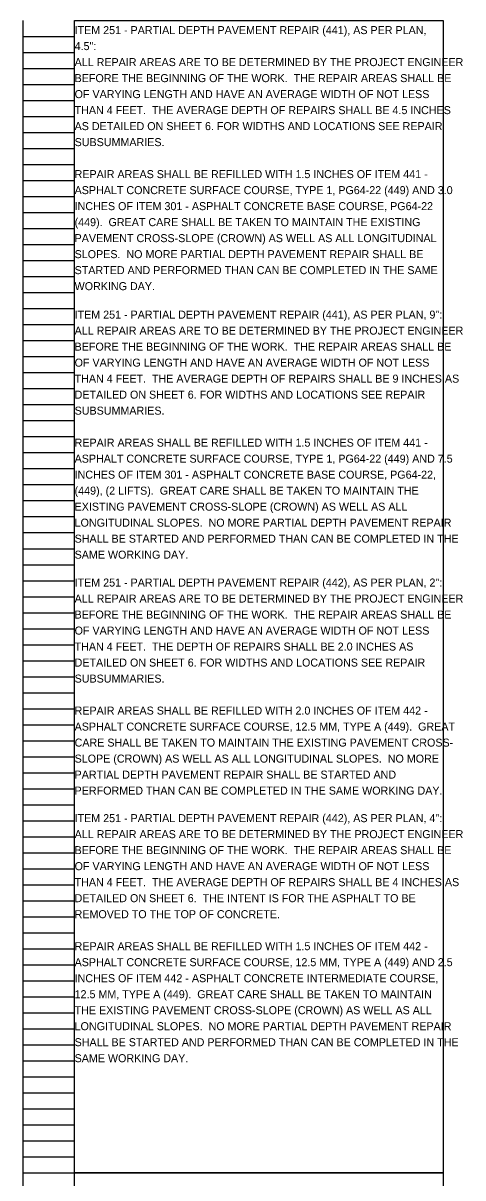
# Model space of a CAD drawing. Extents: x 16463 to 16495, y 5662 to 5823.
# Drawn here: x 16463.05 to 16470.73, y 5783.06 to 5803.27 of the extents above; entities that cross this region are included whole.
import ezdxf

# ---------------------------------------------------------------- set-up
doc = ezdxf.new("R2010")
doc.units = 0
for name, color, linetype in [('Default', 7, 'Continuous'), ('SC_Scratch1', 7, 'Continuous'), ('SH_Data', 7, 'Continuous')]:
    doc.layers.add(name, color=color, linetype=linetype)

msp = doc.modelspace()

# ---------------------------------------------------------------- linework, layer by layer
at = {"layer": 'SC_Scratch1'}
for points in [[(16463.949, 5803.312), (16470.389, 5803.312), (16470.389, 5783.152), (16463.949, 5783.152)], [(16463.949, 5783.152), (16470.389, 5783.152), (16470.389, 5762.992), (16463.949, 5762.992)]]:
    msp.add_lwpolyline(points, close=True, dxfattribs=at)
at = {"layer": 'SH_Data'}
for p, q in [((16463.049, 5783.152), (16463.049, 5803.312)), ((16463.949, 5783.152), (16463.949, 5803.312)), ((16463.049, 5803.032), (16463.949, 5803.032)), ((16463.049, 5802.752), (16463.949, 5802.752)), ((16463.049, 5802.472), (16463.949, 5802.472)), ((16463.049, 5802.192), (16463.949, 5802.192)), ((16463.049, 5801.912), (16463.949, 5801.912)), ((16463.049, 5801.632), (16463.949, 5801.632)), ((16463.049, 5801.352), (16463.949, 5801.352)), ((16463.049, 5801.072), (16463.949, 5801.072)), ((16463.049, 5800.792), (16463.949, 5800.792)), ((16463.049, 5800.512), (16463.949, 5800.512)), ((16463.049, 5800.232), (16463.949, 5800.232)), ((16463.049, 5799.952), (16463.949, 5799.952)), ((16463.049, 5799.672), (16463.949, 5799.672)), ((16463.049, 5799.392), (16463.949, 5799.392)), ((16463.049, 5799.112), (16463.949, 5799.112)), ((16463.049, 5798.832), (16463.949, 5798.832)), ((16463.049, 5798.552), (16463.949, 5798.552)), ((16463.049, 5798.272), (16463.949, 5798.272)), ((16463.049, 5797.992), (16463.949, 5797.992)), ((16463.049, 5797.712), (16463.949, 5797.712)), ((16463.049, 5797.432), (16463.949, 5797.432)), ((16463.049, 5797.152), (16463.949, 5797.152)), ((16463.049, 5796.872), (16463.949, 5796.872)), ((16463.049, 5796.592), (16463.949, 5796.592)), ((16463.049, 5796.312), (16463.949, 5796.312)), ((16463.049, 5796.032), (16463.949, 5796.032)), ((16463.049, 5795.752), (16463.949, 5795.752)), ((16463.049, 5795.472), (16463.949, 5795.472)), ((16463.049, 5795.192), (16463.949, 5795.192)), ((16463.049, 5794.912), (16463.949, 5794.912)), ((16463.049, 5794.632), (16463.949, 5794.632)), ((16463.049, 5794.352), (16463.949, 5794.352)), ((16463.049, 5794.072), (16463.949, 5794.072)), ((16463.049, 5793.792), (16463.949, 5793.792)), ((16463.049, 5793.512), (16463.949, 5793.512)), ((16463.049, 5793.232), (16463.949, 5793.232)), ((16463.049, 5792.952), (16463.949, 5792.952)), ((16463.049, 5792.672), (16463.949, 5792.672)), ((16463.049, 5792.392), (16463.949, 5792.392)), ((16463.049, 5792.112), (16463.949, 5792.112)), ((16463.049, 5791.832), (16463.949, 5791.832)), ((16463.049, 5791.552), (16463.949, 5791.552)), ((16463.049, 5791.272), (16463.949, 5791.272)), ((16463.049, 5790.992), (16463.949, 5790.992)), ((16463.049, 5790.712), (16463.949, 5790.712)), ((16463.049, 5790.432), (16463.949, 5790.432)), ((16463.049, 5790.152), (16463.949, 5790.152)), ((16463.049, 5789.872), (16463.949, 5789.872)), ((16463.049, 5789.592), (16463.949, 5789.592)), ((16463.049, 5789.312), (16463.949, 5789.312)), ((16463.049, 5789.032), (16463.949, 5789.032)), ((16463.049, 5788.752), (16463.949, 5788.752)), ((16463.049, 5788.472), (16463.949, 5788.472)), ((16463.049, 5788.192), (16463.949, 5788.192)), ((16463.049, 5787.912), (16463.949, 5787.912)), ((16463.049, 5787.632), (16463.949, 5787.632)), ((16463.049, 5787.352), (16463.949, 5787.352)), ((16463.049, 5787.072), (16463.949, 5787.072)), ((16463.049, 5786.792), (16463.949, 5786.792)), ((16463.049, 5786.512), (16463.949, 5786.512)), ((16463.049, 5786.232), (16463.949, 5786.232)), ((16463.049, 5785.952), (16463.949, 5785.952)), ((16463.049, 5785.672), (16463.949, 5785.672)), ((16463.049, 5785.392), (16463.949, 5785.392)), ((16463.049, 5785.112), (16463.949, 5785.112)), ((16463.049, 5784.832), (16463.949, 5784.832)), ((16463.049, 5784.552), (16463.949, 5784.552)), ((16463.049, 5784.272), (16463.949, 5784.272)), ((16463.049, 5783.992), (16463.949, 5783.992)), ((16463.049, 5783.712), (16463.949, 5783.712)), ((16463.049, 5783.432), (16463.949, 5783.432)), ((16463.049, 5762.992), (16463.049, 5783.152)), ((16463.049, 5783.152), (16463.949, 5783.152)), ((16463.049, 5783.152), (16463.949, 5783.152)), ((16463.949, 5762.992), (16463.949, 5783.152))]:
    msp.add_line(p, q, dxfattribs=at)

# ---------------------------------------------------------------- texts
at = {"layer": 'Default'}
for s, p in [('ITEM 251 - PARTIAL DEPTH PAVEMENT REPAIR (441), AS PER PLAN, ', (16463.949, 5803.075)), ('4.5":', (16463.949, 5802.795)), ('ALL REPAIR AREAS ARE TO BE DETERMINED BY THE PROJECT ENGINEER ', (16463.949, 5802.515)), ('BEFORE THE BEGINNING OF THE WORK.  THE REPAIR AREAS SHALL BE ', (16463.949, 5802.235)), ('OF VARYING LENGTH AND HAVE AN AVERAGE WIDTH OF NOT LESS ', (16463.949, 5801.955)), ('THAN 4 FEET.  THE AVERAGE DEPTH OF REPAIRS SHALL BE 4.5 INCHES ', (16463.949, 5801.675)), ('AS DETAILED ON SHEET 6. FOR WIDTHS AND LOCATIONS SEE REPAIR ', (16463.949, 5801.395)), ('SUBSUMMARIES.  ', (16463.949, 5801.115)), ('REPAIR AREAS SHALL BE REFILLED WITH 1.5 INCHES OF ITEM 441 - ', (16463.949, 5800.555)), ('ASPHALT CONCRETE SURFACE COURSE, TYPE 1, PG64-22 (449) AND 3.0 ', (16463.949, 5800.275)), ('INCHES OF ITEM 301 - ASPHALT CONCRETE BASE COURSE, PG64-22 ', (16463.949, 5799.995)), ('(449).  GREAT CARE SHALL BE TAKEN TO MAINTAIN THE EXISTING ', (16463.949, 5799.715)), ('PAVEMENT CROSS-SLOPE (CROWN) AS WELL AS ALL LONGITUDINAL ', (16463.949, 5799.435)), ('SLOPES.  NO MORE PARTIAL DEPTH PAVEMENT REPAIR SHALL BE ', (16463.949, 5799.155)), ('STARTED AND PERFORMED THAN CAN BE COMPLETED IN THE SAME ', (16463.949, 5798.875)), ('WORKING DAY.', (16463.949, 5798.595)), ('ITEM 251 - PARTIAL DEPTH PAVEMENT REPAIR (441), AS PER PLAN, 9":', (16463.949, 5798.097)), ('ALL REPAIR AREAS ARE TO BE DETERMINED BY THE PROJECT ENGINEER ', (16463.949, 5797.817)), ('BEFORE THE BEGINNING OF THE WORK.  THE REPAIR AREAS SHALL BE ', (16463.949, 5797.537)), ('OF VARYING LENGTH AND HAVE AN AVERAGE WIDTH OF NOT LESS ', (16463.949, 5797.257)), ('THAN 4 FEET.  THE AVERAGE DEPTH OF REPAIRS SHALL BE 9 INCHES AS ', (16463.949, 5796.977)), ('DETAILED ON SHEET 6. FOR WIDTHS AND LOCATIONS SEE REPAIR ', (16463.949, 5796.697)), ('SUBSUMMARIES.  ', (16463.949, 5796.417)), ('REPAIR AREAS SHALL BE REFILLED WITH 1.5 INCHES OF ITEM 441 - ', (16463.949, 5795.857)), ('ASPHALT CONCRETE SURFACE COURSE, TYPE 1, PG64-22 (449) AND 7.5 ', (16463.949, 5795.577)), ('INCHES OF ITEM 301 - ASPHALT CONCRETE BASE COURSE, PG64-22, ', (16463.949, 5795.297)), ('(449), (2 LIFTS).  GREAT CARE SHALL BE TAKEN TO MAINTAIN THE ', (16463.949, 5795.017)), ('EXISTING PAVEMENT CROSS-SLOPE (CROWN) AS WELL AS ALL ', (16463.949, 5794.737)), ('LONGITUDINAL SLOPES.  NO MORE PARTIAL DEPTH PAVEMENT REPAIR ', (16463.949, 5794.457)), ('SHALL BE STARTED AND PERFORMED THAN CAN BE COMPLETED IN THE ', (16463.949, 5794.177)), ('SAME WORKING DAY.', (16463.949, 5793.897)), ('ITEM 251 - PARTIAL DEPTH PAVEMENT REPAIR (442), AS PER PLAN, 2":', (16463.949, 5793.409)), ('ALL REPAIR AREAS ARE TO BE DETERMINED BY THE PROJECT ENGINEER ', (16463.949, 5793.129)), ('BEFORE THE BEGINNING OF THE WORK.  THE REPAIR AREAS SHALL BE ', (16463.949, 5792.849)), ('OF VARYING LENGTH AND HAVE AN AVERAGE WIDTH OF NOT LESS ', (16463.949, 5792.569)), ('THAN 4 FEET.  THE DEPTH OF REPAIRS SHALL BE 2.0 INCHES AS ', (16463.949, 5792.289)), ('DETAILED ON SHEET 6. FOR WIDTHS AND LOCATIONS SEE REPAIR ', (16463.949, 5792.009)), ('SUBSUMMARIES.  ', (16463.949, 5791.729)), ('REPAIR AREAS SHALL BE REFILLED WITH 2.0 INCHES OF ITEM 442 - ', (16463.949, 5791.169)), ('ASPHALT CONCRETE SURFACE COURSE, 12.5 MM, TYPE A (449).  GREAT ', (16463.949, 5790.889)), ('CARE SHALL BE TAKEN TO MAINTAIN THE EXISTING PAVEMENT CROSS-', (16463.949, 5790.609)), ('SLOPE (CROWN) AS WELL AS ALL LONGITUDINAL SLOPES.  NO MORE ', (16463.949, 5790.329)), ('PARTIAL DEPTH PAVEMENT REPAIR SHALL BE STARTED AND ', (16463.949, 5790.049)), ('PERFORMED THAN CAN BE COMPLETED IN THE SAME WORKING DAY.', (16463.949, 5789.769)), ('ITEM 251 - PARTIAL DEPTH PAVEMENT REPAIR (442), AS PER PLAN, 4":', (16463.949, 5789.287)), ('ALL REPAIR AREAS ARE TO BE DETERMINED BY THE PROJECT ENGINEER ', (16463.949, 5789.007)), ('BEFORE THE BEGINNING OF THE WORK.  THE REPAIR AREAS SHALL BE ', (16463.949, 5788.727)), ('OF VARYING LENGTH AND HAVE AN AVERAGE WIDTH OF NOT LESS ', (16463.949, 5788.447)), ('THAN 4 FEET.  THE AVERAGE DEPTH OF REPAIRS SHALL BE 4 INCHES AS ', (16463.949, 5788.167)), ('DETAILED ON SHEET 6.  THE INTENT IS FOR THE ASPHALT TO BE ', (16463.949, 5787.887)), ('REMOVED TO THE TOP OF CONCRETE.', (16463.949, 5787.607)), ('REPAIR AREAS SHALL BE REFILLED WITH 1.5 INCHES OF ITEM 442 - ', (16463.949, 5787.047)), ('ASPHALT CONCRETE SURFACE COURSE, 12.5 MM, TYPE A (449) AND 2.5 ', (16463.949, 5786.767)), ('INCHES OF ITEM 442 - ASPHALT CONCRETE INTERMEDIATE COURSE, ', (16463.949, 5786.487)), ('12.5 MM, TYPE A (449).  GREAT CARE SHALL BE TAKEN TO MAINTAIN ', (16463.949, 5786.207)), ('THE EXISTING PAVEMENT CROSS-SLOPE (CROWN) AS WELL AS ALL ', (16463.949, 5785.927)), ('LONGITUDINAL SLOPES.  NO MORE PARTIAL DEPTH PAVEMENT REPAIR ', (16463.949, 5785.647)), ('SHALL BE STARTED AND PERFORMED THAN CAN BE COMPLETED IN THE ', (16463.949, 5785.367)), ('SAME WORKING DAY.', (16463.949, 5785.087))]:
    msp.add_text(s, height=0.14, dxfattribs=at).set_placement(p)

doc.saveas('drawing.dxf')
